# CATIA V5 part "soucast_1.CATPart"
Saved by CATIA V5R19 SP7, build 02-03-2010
Part number: Part1
Material "Steel": density 7860 kg/m3, Young's modulus 2e+11 Pa, Poisson ratio 0.266, thermal expansion 1.17e-05 1/K
Bounding box of the stored display mesh (mm): x -80 to 80, y -80 to 80, z 0 to 80
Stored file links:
  D:\CATIA\TECHNODAT\FEM_TESTOVANI\SROUBOVY_SPOJ\soucast_1.CATPart
  C:\Program Files\Dassault Systemes\B19\win_b64\reffiles\standard\MetricThickPitch.txt
  C:\Program Files\Dassault Systemes\B19\win_b64\startup\materials\Catalog.CATMaterial
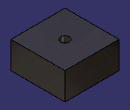
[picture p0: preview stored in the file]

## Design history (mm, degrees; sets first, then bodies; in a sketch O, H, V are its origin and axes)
Body1 (main body), material "Steel"
  Sketch1 on xy-plane, origin (0, 0, 0), H (1, 0, 0), V (0, 1, 0)
    line L1 (80, 80) -> (80, -80)
    line L2 (80, -80) -> (-80, -80)
    line L3 (-80, -80) -> (-80, 80)
    line L4 (-80, 80) -> (80, 80)
    vertical: L1 V, L3 V
    horizontal: L2 H, L4 H
    equidistance: L1 L3 O, L2 L4 O
  Pad1: profile Sketch1, direction (0, 0, 1), length 80
  Sketch2 on end face of Pad1, origin (0, 0, 80), H (1, 0, 0), V (0, 1, 0)
    point P1 (0, 0)
  Hole1: placed by Sketch2, at (0, 0, 80) direction (0, 0, -1), diameter 26.211, depth 60, V-bottom angle 120, threaded "M30", thread diameter 30, thread depth 30, pitch 3.5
